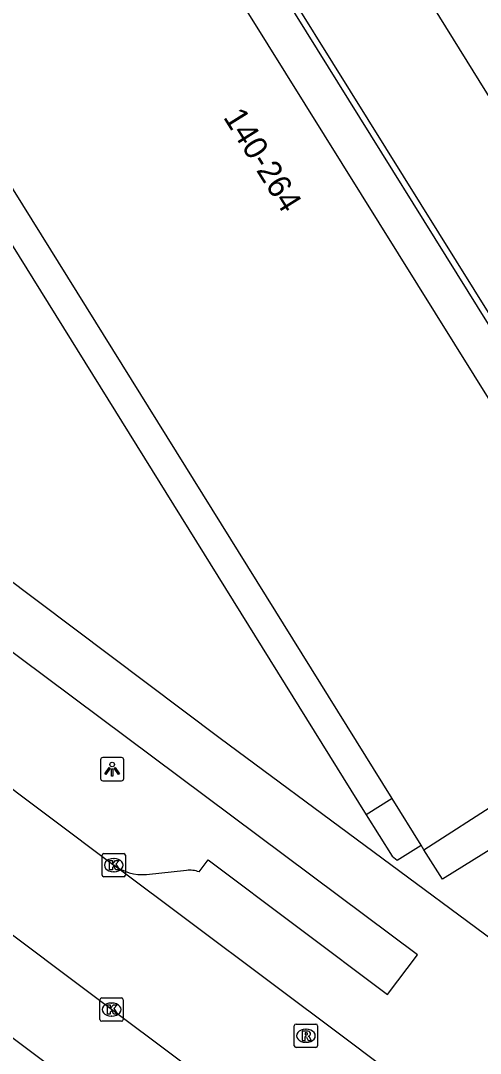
# Model space of a CAD drawing. Extents: x 159888 to 160757, y 384031 to 384746.
# Drawn here: x 160065.5 to 160085.2, y 384500.33 to 384544.62 of the extents above; entities that cross this region are included whole.
import ezdxf

# ---------------------------------------------------------------- set-up
doc = ezdxf.new("R2010")
doc.units = 0
for name, color, linetype in [('IMGEO_Fietspad_gesloten', 7, 'Continuous'), ('IMGEO_Kolk', 7, 'Continuous'), ('IMGEO_Lichtpunt', 7, 'Continuous'), ('IMGEO_Pand', 7, 'Continuous'), ('IMGEO_Pand_nummerreeks', 7, 'Continuous'), ('IMGEO_Rijbaan_lokaal_open', 7, 'Continuous'), ('IMGEO_Rioolput', 7, 'Continuous'), ('IMGEO_Voetpad_open', 7, 'Continuous')]:
    doc.layers.add(name, color=color, linetype=linetype)

msp = doc.modelspace()

# ---------------------------------------------------------------- linework, layer by layer
at = {"layer": 'IMGEO_Fietspad_gesloten'}
msp.add_lwpolyline([(160106.003, 384470.24), (160105.836, 384470.365), (160031.234, 384526.495), (160017.533, 384536.804)], dxfattribs=at)
at = {"layer": 'IMGEO_Kolk'}
for p, q in [((160068.991, 384507.973), (160068.991, 384508.825)), ((160069.066, 384508.899), (160069.918, 384508.899)), ((160069.479, 384508.679), (160069.504, 384508.679)), ((160069.992, 384508.825), (160069.992, 384507.973)), ((160069.918, 384507.899), (160069.066, 384507.899)), ((160069.502, 384508.119), (160069.477, 384508.119)), ((160068.899, 384501.778), (160068.899, 384502.63)), ((160068.974, 384502.704), (160069.826, 384502.704)), ((160069.387, 384502.484), (160069.412, 384502.484)), ((160069.9, 384502.63), (160069.9, 384501.778)), ((160069.826, 384501.704), (160068.974, 384501.704)), ((160069.41, 384501.924), (160069.385, 384501.924))]:
    msp.add_line(p, q, dxfattribs=at)
for points in [[(160068.991, 384507.973), (160068.991, 384508.825)], [(160069.066, 384508.899), (160069.918, 384508.899)], [(160069.992, 384508.825), (160069.992, 384507.973)], [(160069.312, 384508.599), (160069.435, 384508.599), (160069.435, 384508.448), (160069.565, 384508.599), (160069.729, 384508.599), (160069.583, 384508.448), (160069.736, 384508.199), (160069.584, 384508.199), (160069.499, 384508.363), (160069.435, 384508.296), (160069.435, 384508.199), (160069.312, 384508.199), (160069.312, 384508.599)], [(160069.918, 384507.899), (160069.066, 384507.899)], [(160068.899, 384501.778), (160068.899, 384502.63)], [(160068.974, 384502.704), (160069.826, 384502.704)], [(160069.9, 384502.63), (160069.9, 384501.778)], [(160069.22, 384502.404), (160069.343, 384502.404), (160069.343, 384502.253), (160069.473, 384502.404), (160069.637, 384502.404), (160069.491, 384502.253), (160069.644, 384502.004), (160069.492, 384502.004), (160069.407, 384502.168), (160069.343, 384502.101), (160069.343, 384502.004), (160069.22, 384502.004), (160069.22, 384502.404)], [(160069.826, 384501.704), (160068.974, 384501.704)]]:
    msp.add_lwpolyline(points, dxfattribs=at)
for centre, start, end in [((160069.068, 384508.823), 91.552, 178.448), ((160069.068, 384508.823), 91.552, 178.448), ((160069.916, 384508.823), 1.552, 88.448), ((160069.916, 384508.823), 1.552, 88.448), ((160069.068, 384507.975), 181.552, 268.448), ((160069.068, 384507.975), 181.552, 268.448), ((160069.916, 384507.975), 271.552, 358.448), ((160069.916, 384507.975), 271.552, 358.448), ((160068.976, 384502.628), 91.552, 178.448), ((160068.976, 384502.628), 91.552, 178.448), ((160069.824, 384502.628), 1.552, 88.448), ((160069.824, 384502.628), 1.552, 88.448), ((160068.976, 384501.78), 181.552, 268.448), ((160068.976, 384501.78), 181.552, 268.448), ((160069.824, 384501.78), 271.552, 358.448), ((160069.824, 384501.78), 271.552, 358.448)]:
    msp.add_arc(centre, 0.0765, start, end, dxfattribs=at)
for centre, major_axis, ratio, start_param, end_param in [((160069.478, 384508.399), (-0.387, 0.002), 0.722429, 4.712389, 7.853982), ((160069.503, 384508.399), (-0.39, 0.002), 0.717154, 1.570796, 4.712389), ((160069.386, 384502.204), (-0.387, 0.002), 0.722429, 4.712389, 7.853982), ((160069.411, 384502.204), (-0.39, 0.002), 0.717154, 1.570796, 4.712389)]:
    msp.add_ellipse(centre, major_axis=major_axis, ratio=ratio, start_param=start_param, end_param=end_param, dxfattribs=at)
at = {"layer": 'IMGEO_Lichtpunt'}
for p, q in [((160068.923, 384512.92), (160068.923, 384512.113)), ((160068.923, 384512.92), (160068.923, 384512.113)), ((160069.825, 384513.015), (160069.017, 384513.015)), ((160069.825, 384513.015), (160069.017, 384513.015)), ((160069.919, 384512.113), (160069.919, 384512.92)), ((160069.919, 384512.113), (160069.919, 384512.92)), ((160069.017, 384512.019), (160069.825, 384512.019)), ((160069.017, 384512.019), (160069.825, 384512.019))]:
    msp.add_line(p, q, dxfattribs=at)
for points in [[(160069.297, 384512.584), (160069.336, 384512.556), (160069.148, 384512.294), (160069.11, 384512.321), (160069.297, 384512.584)], [(160069.399, 384512.536), (160069.446, 384512.536), (160069.446, 384512.214), (160069.399, 384512.214), (160069.399, 384512.536)], [(160069.509, 384512.556), (160069.547, 384512.583), (160069.734, 384512.321), (160069.695, 384512.293), (160069.509, 384512.556)]]:
    msp.add_lwpolyline(points, dxfattribs=at)
msp.add_circle((160069.422, 384512.718), 0.0994, dxfattribs=at)
for centre, start, end in [((160069.017, 384512.92), 90, 180), ((160069.017, 384512.92), 90, 180), ((160069.825, 384512.92), 0, 90), ((160069.825, 384512.92), 0, 90), ((160069.017, 384512.113), 180, 270), ((160069.017, 384512.113), 180, 270), ((160069.825, 384512.113), 270, 0), ((160069.825, 384512.113), 270, 360)]:
    msp.add_arc(centre, 0.0946, start, end, dxfattribs=at)
at = {"layer": 'IMGEO_Pand'}
for points in [[(160070.432, 384552.675), (160088.916, 384522.994), (160090.34, 384523.871)], [(160081.418, 384511.253), (160058.271, 384548.509)], [(160082.785, 384509.053), (160095.752, 384517.41)], [(160082.66, 384509.254), (160081.418, 384511.253)], [(160082.785, 384509.053), (160082.66, 384509.254)]]:
    msp.add_lwpolyline(points, dxfattribs=at)
at = {"layer": 'IMGEO_Rijbaan_lokaal_open'}
for points in [[(160093.724, 384528.242), (160078.34, 384553.049)], [(160101.659, 384477.982), (160099.829, 384479.351), (160085.029, 384490.505), (160069.4, 384502.204), (160052.141, 384515.156), (160036.065, 384527.255), (160033.506, 384529.181), (160026.846, 384534.194), (160022.615, 384537.386), (160020.244, 384539.075), (160018.872, 384540.033)], [(160055.316, 384519.049), (160055.524, 384518.887), (160069.487, 384508.403)], [(160081.935, 384499.068), (160079.45, 384500.937), (160069.487, 384508.403)]]:
    msp.add_lwpolyline(points, dxfattribs=at)
at = {"layer": 'IMGEO_Rioolput'}
for p, q in [((160077.302, 384501.583), (160078.154, 384501.583)), ((160077.227, 384500.657), (160077.227, 384501.509)), ((160077.715, 384501.363), (160077.74, 384501.363)), ((160078.228, 384501.509), (160078.228, 384500.657)), ((160077.738, 384500.803), (160077.713, 384500.803)), ((160078.154, 384500.583), (160077.302, 384500.583))]:
    msp.add_line(p, q, dxfattribs=at)
for points in [[(160077.302, 384501.583), (160078.154, 384501.583)], [(160077.227, 384500.657), (160077.227, 384501.509)], [(160077.816, 384501.281), (160077.564, 384501.283), (160077.564, 384500.883)], [(160077.742, 384501.202), (160077.688, 384501.202), (160077.688, 384501.121)], [(160078.228, 384501.509), (160078.228, 384500.657)], [(160077.564, 384500.883), (160077.688, 384500.883), (160077.688, 384501.045), (160077.699, 384501.045)], [(160077.688, 384501.121), (160077.74, 384501.121)], [(160077.746, 384501.016), (160077.817, 384500.883), (160077.957, 384500.883), (160077.892, 384501.009)], [(160078.154, 384500.583), (160077.302, 384500.583)]]:
    msp.add_lwpolyline(points, dxfattribs=at)
for centre, radius, start, end in [((160077.304, 384501.507), 0.0765, 91.552, 178.448), ((160077.304, 384501.507), 0.0765, 91.552, 178.448), ((160078.152, 384501.507), 0.0765, 1.552, 88.448), ((160078.152, 384501.507), 0.0765, 1.552, 88.448), ((160077.748, 384501.106), 0.0964, 77.0061, 93.1865), ((160077.762, 384501.163), 0.0378, 276.6634, 79.6772), ((160077.815, 384501.171), 0.109, 350.3612, 89.416), ((160077.813, 384501.171), 0.112, 277.5842, 350.9817), ((160077.698, 384500.992), 0.0533, 26.0293, 88.6989), ((160077.724, 384501.31), 0.19, 274.7715, 282.9687), ((160077.797, 384500.956), 0.108, 29.5134, 73.7905), ((160077.304, 384500.659), 0.0765, 181.552, 268.448), ((160077.304, 384500.659), 0.0765, 181.552, 268.448), ((160078.152, 384500.659), 0.0765, 271.552, 358.448), ((160078.152, 384500.659), 0.0765, 271.552, 358.448)]:
    msp.add_arc(centre, radius, start, end, dxfattribs=at)
for centre, major_axis, ratio, start_param, end_param in [((160077.714, 384501.083), (-0.387, 0.002), 0.722429, 4.712389, 7.853982), ((160077.739, 384501.083), (-0.39, 0.002), 0.717154, 1.570796, 4.712389)]:
    msp.add_ellipse(centre, major_axis=major_axis, ratio=ratio, start_param=start_param, end_param=end_param, dxfattribs=at)
at = {"layer": 'IMGEO_Voetpad_open'}
for points in [[(160074.252, 384550.23), (160074.041, 384550.098), (160089.71, 384524.905)], [(160074.252, 384550.23), (160089.532, 384525.678), (160093.724, 384528.242)], [(160058.271, 384548.509), (160057.163, 384547.816), (160080.309, 384510.56)], [(160112.975, 384485.03), (160092.698, 384500.015), (160074.056, 384513.832), (160058.403, 384525.598), (160044.048, 384536.578), (160039.158, 384540.572)], [(160073.152, 384508.109), (160073.541, 384508.626), (160081.229, 384502.849), (160082.505, 384504.558), (160063.2, 384518.984), (160063.554, 384519.484), (160058.511, 384523.2), (160055.316, 384519.049)], [(160081.418, 384511.253), (160080.309, 384510.56)], [(160080.309, 384510.56), (160081.416, 384508.779), (160081.635, 384508.614), (160082.66, 384509.254)], [(160087.531, 384510.255), (160083.576, 384507.794), (160082.785, 384509.053)], [(160070.9, 384507.996), (160072.606, 384508.178)]]:
    msp.add_lwpolyline(points, dxfattribs=at)
for centre, radius, start, end in [((160070.762, 384510.175), 2.183, 234.2491, 273.6139), ((160072.732, 384506.976), 1.208, 69.6326, 95.9624)]:
    msp.add_arc(centre, radius, start, end, dxfattribs=at)

# ---------------------------------------------------------------- texts
at = {"layer": 'IMGEO_Pand_nummerreeks'}
msp.add_text('140-264', height=1, rotation=301.9134, dxfattribs=at).set_placement((160074.161, 384540.481))

doc.saveas('drawing.dxf')
